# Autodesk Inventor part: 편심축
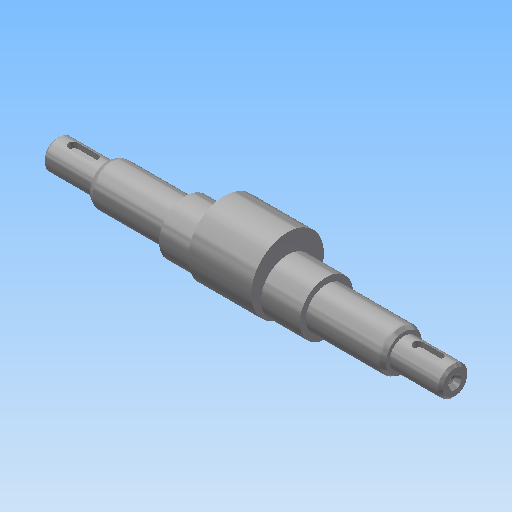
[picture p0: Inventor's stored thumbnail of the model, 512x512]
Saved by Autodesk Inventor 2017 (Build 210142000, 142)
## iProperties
Created: 2019-01
Part Number: 편심축
Material: 강철, 연강
Document SubType Name: Modeling
Designer: mduedu
Density: 7.86 g/cm^3
Appearance: 강철
Mass: 387.265 g
Surface Area: 112.621 cm^2
Volume: 49.2703 cm^3
Author: mduedu
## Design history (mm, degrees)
sketch "스케치1"
  geometry: L1 (0, 0)-(21, 0); L2 (21, 0)-(21, 6); L3 (21, 6)-(0, 6); L4 (0, 6)-(0, 0); L5 (21, 0)-(53, 0); L6 (53, 0)-(53, 8.5); L7 (53, 8.5)-(21, 8.5); L8 (21, 8.5)-(21, 0); L9 (53, 0)-(111, 0); L10 (111, 0)-(111, 11); L11 (111, 11)-(53, 11); L12 (53, 11)-(53, 0); L13 (82, 11)-(82, 0); L14 (111, 0)-(143, 0); L15 (143, 0)-(143, 8.5); L16 (143, 8.5)-(111, 8.5); L17 (111, 8.5)-(111, 0); L18 (143, 0)-(164, 0); L19 (164, 0)-(164, 6); L20 (164, 6)-(143, 6); L21 (143, 6)-(143, 0)
  constraints: 42 end point, 10 parallel, 5 horizontal, 5 perpendicular, 4 collinear, 2 midpoint
  dimensions: "d3" = 58 distance of L10.end L11.end; "d5" = 12 diameter of L3 L1; "d6" = 17 diameter of L7 L5; "d8" = 22 diameter of L11 L9; "d51" = 164 distance between parallel lines of L4 L19; "d52" = 122 distance between parallel lines of L2 L15; "d53" = 32 distance of L15.end L16.end (derived); "d54" = 32 distance of L6.end L7.end (derived)
revolve "회전1" sketch "스케치1" stored, may be unused: angle "d9" = 90 deg
node "작업 평면3"
sketch "스케치2"
  geometry: C1 r 15 at (0, 4); C2 r 11 at (0, 0); 1 further point
  constraints: 2 centre point, 1 tangent, 1 vertical alignment
  dimensions: "d11" = 4 distance of point (0, 0) C1.centre
extrude "돌출1" join sketch "스케치2" distance "d12" = 26; taper "d13" = 0 deg
node "작업 평면2"
sketch "스케치3" dims "d16" = 12
  geometry: L1 (-4.5, 2)-(3.5, 2); L2 (3.5, 2)-(3.5, -2); L3 (3.5, -2)-(-4.5, -2); L4 (-4.5, -2)-(-4.5, 2); L5 (-10.5, 8.5)-(-10.5, -8.5) reference; 3 further points
  constraints: 8 end point, 2 midpoint, 2 parallel, 2 vertical alignment, 1 horizontal, 1 horizontal alignment, 1 perpendicular, 4 other
  dimensions: "d14" = 4 distance between parallel lines of L3 L1; "d17" = 4 dimension on L5
extrude "돌출2" cut sketch "스케치3" distance "d18" = 2.5; taper "d19" = 0 deg
node "작업 평면4"
chamfer "모따기1" distance "d20" = 1.82; stored, may be unused: second distance "d21" = 2, angle "d22" = 30 deg
chamfer "모따기3" distance "d56" = 1.82; stored, may be unused: second distance "d57" = 2, angle "d58" = 30 deg
fillet "모깎기1" dims "d23" = 2
hole "구멍2" diameter "d39" = 3.242; stored, may be unused: countersink angle "d43" = 60 deg, drill point angle "d45" = 118 deg; dims "d37" = 10, "d38" = 10, "d40" = 8, "d41" = 5.51, "d42" = 2, "d44" = 10
sketch "스케치5"
  geometry: L1 (0, 0)-(2, 0); L2 (2, 0)-(2, 1.621); L3 (0, 2.776)-(0, 0); L4 (0, 2.776)-(2, 1.621); L5 (10, 1.621)-(0, 1.621) reference
  constraints: 8 end point, 1 horizontal, 1 parallel, 1 perpendicular, 1 point on line
  dimensions: "d46" = 2 distance between parallel lines of L2 L3; "d48" = 30 deg angle of L4 L1
revolve "회전2" sketch "스케치5" stored, may be unused: angle "d50" = 90 deg
chamfer "모따기2" distance "d25" = 1; stored, may be unused: second distance "d26" = 2, angle "d27" = 30 deg
node "솔리드1"
mirror "대칭1"
mirror "대칭2"
mirror "대칭3"
other parameters: "d55" = -16
